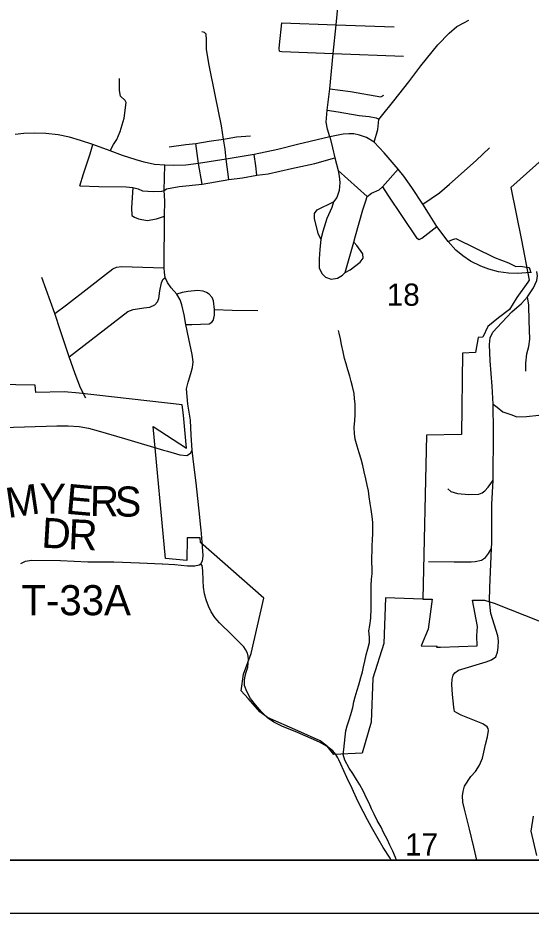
# Model space of a CAD drawing. Extents: x 0 to 34, y 0 to 22.
# Drawn here: x 7.23 to 8.199, y 14 to 15.691 of the extents above; entities that cross this region are included whole.
import ezdxf

# ---------------------------------------------------------------- set-up
doc = ezdxf.new("R2010")
doc.units = 0
for name, color, linetype in [('GM_X_City_Street', 7, 'Continuous'), ('GM_X_Corporation', 7, 'Continuous'), ('GM_X_County_Road', 7, 'Continuous'), ('GM_X_Minor_River', 7, 'Continuous'), ('GM_X_Section_Text', 7, 'Continuous'), ('GM_X_State_Route', 7, 'Continuous'), ('GM_X_Township_Road', 7, 'Continuous'), ('GM_X_Township_Road_Text', 7, 'Continuous'), ('SH_Data', 7, 'Continuous')]:
    doc.layers.add(name, color=color, linetype=linetype)

msp = doc.modelspace()

# ---------------------------------------------------------------- linework, layer by layer
at = {"layer": 'GM_X_City_Street'}
msp.add_line((7.8345, 15.4031), (7.8892, 15.3538), dxfattribs=at)
for points in [[(7.819, 15.4661), (7.8146, 15.4811), (7.8118, 15.4943), (7.8136, 15.5166), (7.8185, 15.5572), (7.8249, 15.6239), (7.8306, 15.6782), (7.8348, 15.7167), (7.8392, 15.7584)], [(7.7236, 15.6285), (7.7232, 15.633), (7.7235, 15.6404), (7.7281, 15.682)], [(7.7281, 15.682), (7.8306, 15.6782), (7.9406, 15.674)], [(7.9026, 15.4564), (7.9093, 15.4801), (7.9116, 15.499), (7.9167, 15.5054), (7.9399, 15.5344), (7.9683, 15.5703), (7.9906, 15.6003), (8.0229, 15.6404), (8.0442, 15.6623), (8.0588, 15.675), (8.0722, 15.682), (8.0815, 15.6868)], [(7.6279, 15.3857), (7.6231, 15.4243), (7.6208, 15.443), (7.6179, 15.4621), (7.6144, 15.4874), (7.6022, 15.5458), (7.5909, 15.602), (7.5859, 15.6311), (7.586, 15.6499), (7.5854, 15.6602), (7.5818, 15.6634), (7.577, 15.6647)], [(7.7236, 15.6285), (7.728, 15.6274), (7.8249, 15.6239), (7.9581, 15.6189)], [(7.404, 15.4399), (7.41, 15.452), (7.4165, 15.4614), (7.4225, 15.4767), (7.4302, 15.5015), (7.434, 15.531), (7.4321, 15.5353), (7.4233, 15.5434), (7.4213, 15.5538), (7.4215, 15.5766)], [(7.8185, 15.5572), (7.8576, 15.552), (7.9151, 15.5419), (7.9205, 15.5454)], [(7.8136, 15.5166), (7.8346, 15.5134), (7.8744, 15.5068), (7.8934, 15.5049), (7.9065, 15.5022), (7.9098, 15.5007), (7.9116, 15.499)], [(7.5156, 15.4475), (7.5467, 15.4517), (7.5655, 15.4538), (7.5907, 15.4583), (7.6179, 15.4621), (7.6427, 15.4664), (7.6688, 15.4681)], [(7.819, 15.4661), (7.8236, 15.4458), (7.8281, 15.4268), (7.8345, 15.4031), (7.8365, 15.3919), (7.8379, 15.3799), (7.8366, 15.3652), (7.8322, 15.3519), (7.826, 15.3437), (7.8223, 15.3331), (7.8132, 15.3119), (7.8056, 15.2874), (7.8015, 15.2734), (7.7997, 15.2537), (7.7984, 15.236), (7.7988, 15.219), (7.8034, 15.2084), (7.8106, 15.2012), (7.8216, 15.1978), (7.8332, 15.1993), (7.8428, 15.2048), (7.8475, 15.2099), (7.8642, 15.2676), (7.8673, 15.2793), (7.8813, 15.3287), (7.8865, 15.3458), (7.8892, 15.3538), (7.8977, 15.3599), (7.9122, 15.3665), (7.9182, 15.3717), (7.9478, 15.4051)], [(7.3463, 15.374), (7.3533, 15.3964), (7.3661, 15.4346), (7.371, 15.4519)], [(7.5774, 15.3768), (7.5707, 15.416), (7.5655, 15.4538)], [(7.9942, 15.3392), (8.0258, 15.3604), (8.0446, 15.3769), (8.0952, 15.4217), (8.1201, 15.4458)], [(7.5061, 15.3653), (7.5103, 15.3684), (7.5344, 15.3725), (7.5774, 15.3768), (7.6279, 15.3857), (7.6537, 15.3888), (7.6811, 15.3942), (7.7024, 15.3968), (7.7466, 15.4065), (7.7903, 15.416), (7.8281, 15.4268)], [(7.6811, 15.3942), (7.6793, 15.4119), (7.6761, 15.4333)], [(7.3463, 15.374), (7.3825, 15.3725), (7.434, 15.3718), (7.4464, 15.3705), (7.457, 15.3684), (7.4651, 15.3647), (7.485, 15.3634), (7.5017, 15.3638), (7.5061, 15.3653)], [(7.4464, 15.3705), (7.4441, 15.3324), (7.445, 15.318), (7.4497, 15.3146), (7.4577, 15.3114), (7.4736, 15.3085), (7.4914, 15.3118), (7.5068, 15.3168)], [(7.9182, 15.3717), (7.9283, 15.356), (7.9828, 15.2753), (7.9873, 15.2726), (7.9923, 15.2747), (8.021, 15.2971)], [(7.8015, 15.2734), (7.797, 15.2839), (7.7896, 15.312), (7.7901, 15.3216), (7.7951, 15.3284), (7.826, 15.3437)], [(8.0423, 15.2685), (8.0494, 15.272), (8.0567, 15.2746), (8.1296, 15.2384), (8.1565, 15.2282), (8.17, 15.2215), (8.1793, 15.2219), (8.1897, 15.2204), (8.1946, 15.2194), (8.1968, 15.2166), (8.198, 15.21)], [(7.8475, 15.2099), (7.8569, 15.2152), (7.8763, 15.2294), (7.882, 15.2375), (7.8814, 15.2452), (7.8701, 15.2612), (7.8642, 15.2676)], [(7.2994, 15.1329), (7.3211, 15.1488), (7.3638, 15.1818), (7.3949, 15.2064), (7.4086, 15.2171), (7.4161, 15.2203), (7.425, 15.2212), (7.5058, 15.2191)], [(8.1204, 14.5894), (8.1209, 14.6149), (8.124, 14.6886), (8.1249, 14.6997), (8.1249, 14.7277), (8.1247, 14.7721), (8.1276, 14.8181), (8.1279, 14.9095), (8.1272, 14.9616), (8.1252, 14.9952), (8.1218, 15.043), (8.1204, 15.0739), (8.1215, 15.0866), (8.1267, 15.0972), (8.1439, 15.1155), (8.1627, 15.1358), (8.1807, 15.1518), (8.1921, 15.1642), (8.2034, 15.1813), (8.21, 15.1948), (8.2108, 15.2036), (8.2097, 15.2121)], [(7.358, 14.9728), (7.3476, 14.9925), (7.3377, 15.0186), (7.3266, 15.051), (7.3102, 15.0999), (7.2994, 15.1329), (7.2748, 15.2007)], [(7.3266, 15.051), (7.437, 15.1363), (7.4472, 15.1404), (7.4674, 15.1434), (7.4788, 15.1448), (7.4884, 15.1489), (7.4934, 15.1544), (7.4959, 15.1613), (7.4975, 15.1752), (7.5007, 15.1907), (7.5032, 15.1971), (7.5077, 15.2007)], [(7.5471, 15.1117), (7.5584, 15.1121), (7.5911, 15.1133), (7.5961, 15.1163), (7.5985, 15.1194), (7.6, 15.1241), (7.6007, 15.1296), (7.6011, 15.1402), (7.5989, 15.1564), (7.5965, 15.1631), (7.5909, 15.1693), (7.5859, 15.1724), (7.5796, 15.175), (7.5686, 15.1761), (7.5513, 15.1744), (7.5397, 15.1725), (7.5297, 15.1691)], [(8.1891, 15.0239), (8.1893, 15.0386), (8.1911, 15.0566), (8.195, 15.0701), (8.1968, 15.0841), (8.1954, 15.1185), (8.1944, 15.1485), (8.1921, 15.1642)], [(7.6011, 15.1402), (7.6346, 15.1387), (7.683, 15.1384)], [(8.1272, 14.9616), (8.1347, 14.9558), (8.1454, 14.9471), (8.1608, 14.9416), (8.1721, 14.9376), (8.1904, 14.938), (8.2139, 14.9407)], [(8.042, 14.8013), (8.0476, 14.7966), (8.0601, 14.7924), (8.0815, 14.7908), (8.1004, 14.7916), (8.1064, 14.7941), (8.1116, 14.7975), (8.1179, 14.8043), (8.1229, 14.8113), (8.1276, 14.8181)], [(8.0054, 14.6639), (8.0536, 14.6635), (8.0767, 14.6634), (8.086, 14.6636), (8.0935, 14.6642), (8.1055, 14.6669), (8.113, 14.6717), (8.1183, 14.6791), (8.124, 14.6886)]]:
    msp.add_lwpolyline(points, dxfattribs=at)
at = {"layer": 'GM_X_Corporation'}
for points in [[(4.5503, 14.1), (8.9, 14.1), (8.9, 15.6953), (8.4164, 15.7046), (8.4088, 15.7047), (8.2556, 15.7096), (8.2436, 15.7079), (8.2379, 15.708), (7.8346, 15.7173), (7.3532, 15.7283), (7.2238, 15.7321), (7.2174, 15.7331), (7.1916, 15.7337), (7.0294, 15.7382), (6.9267, 15.7411), (6.8653, 15.7428), (6.8105, 15.7443), (6.4702, 15.7474), (5.7944, 15.7634), (5.6123, 15.7657), (5.6068, 15.7657), (5.6014, 15.7658), (5.4664, 15.7674)], [(8.2554, 15.4553), (8.1604, 15.3705), (8.1807, 15.2712), (8.1955, 15.1955), (8.1929, 15.1917), (8.1718, 15.1627), (8.1582, 15.14), (8.1376, 15.1245), (8.1175, 15.108), (8.1077, 15.0882), (8.0992, 15.0873), (8.0942, 15.059), (8.0692, 15.058), (8.0677, 14.9042), (8.0011, 14.9029), (7.9943, 14.5933), (7.9241, 14.5958), (7.9211, 14.5094), (7.8998, 14.4439), (7.8968, 14.3609), (7.88, 14.3022), (7.8265, 14.2995), (7.8137, 14.3155), (7.8003, 14.3256), (7.7585, 14.3443), (7.7009, 14.3696), (7.6864, 14.38), (7.6648, 14.4053), (7.6516, 14.4201), (7.6558, 14.4513), (7.6701, 14.4906), (7.6944, 14.5951), (7.5746, 14.7003), (7.5738, 14.7092), (7.5496, 14.7086), (7.5487, 14.6662), (7.5081, 14.67), (7.4849, 14.9192), (7.5483, 14.878), (7.5426, 14.9403), (7.5396, 14.96), (7.3453, 14.982), (7.3172, 14.9845), (7.2635, 14.9834), (7.2621, 14.9971), (7.0789, 15.0004)], [(8.2554, 15.4553), (8.1604, 15.3705), (8.1807, 15.2712), (8.1955, 15.1955), (8.1929, 15.1917), (8.1718, 15.1627), (8.1582, 15.14), (8.1376, 15.1245), (8.1175, 15.108), (8.1077, 15.0882), (8.0992, 15.0873), (8.0942, 15.059), (8.0692, 15.058), (8.0677, 14.9042), (8.0011, 14.9029), (7.9943, 14.5933), (8.0119, 14.5929), (8.0044, 14.5363), (7.9916, 14.5046), (8.0213, 14.504), (8.0206, 14.5025), (8.0249, 14.5024), (8.028, 14.5025), (8.0971, 14.5048), (8.0965, 14.5235), (8.0978, 14.5412), (8.0881, 14.5914), (8.1109, 14.591), (8.1291, 14.5852), (8.2738, 14.5284)], [(8.2032, 14.1833), (8.1986, 14.1545), (8.2091, 14.1089)]]:
    msp.add_lwpolyline(points, dxfattribs=at)
at = {"layer": 'GM_X_County_Road'}
msp.add_line((7.5586, 14.8746), (7.5571, 14.9028), dxfattribs=at)
for points in [[(7.5516, 15.0046), (7.5564, 15.0194), (7.5593, 15.0305), (7.5604, 15.0415), (7.5593, 15.0511), (7.5588, 15.0551), (7.5525, 15.0849), (7.5471, 15.1117), (7.5434, 15.1299), (7.5392, 15.1492), (7.5363, 15.1583), (7.5297, 15.1691), (7.5191, 15.181), (7.512, 15.1915), (7.5077, 15.2007), (7.5063, 15.21), (7.5058, 15.2191), (7.5068, 15.3168), (7.507, 15.3455), (7.5061, 15.3653), (7.5069, 15.4128)], [(7.5571, 14.9028), (7.5555, 14.931), (7.5508, 14.9615), (7.5495, 14.9758), (7.5481, 14.9903), (7.551, 15.0028), (7.5516, 15.0046)], [(7.2014, 14.9171), (7.3033, 14.9206), (7.3248, 14.9206), (7.3453, 14.9191), (7.3632, 14.9158), (7.3815, 14.9111), (7.4311, 14.8965), (7.5045, 14.8746)], [(7.5045, 14.8746), (7.5123, 14.8723), (7.5357, 14.8659), (7.5486, 14.8646), (7.5559, 14.8689), (7.5586, 14.8746)]]:
    msp.add_lwpolyline(points, dxfattribs=at)
at = {"layer": 'GM_X_Minor_River'}
for points in [[(7.9275, 14.1381), (7.9204, 14.1525), (7.9156, 14.1622), (7.9085, 14.175), (7.9026, 14.1867), (7.8978, 14.1969), (7.8931, 14.2074), (7.8883, 14.2172), (7.8823, 14.23), (7.8753, 14.2425), (7.8694, 14.2522), (7.8623, 14.2635), (7.8556, 14.274), (7.8473, 14.2887), (7.8441, 14.2993), (7.845, 14.3092), (7.8467, 14.321), (7.8476, 14.3328), (7.8492, 14.3442), (7.8517, 14.3538), (7.8556, 14.3653), (7.8585, 14.3752), (7.862, 14.3886), (7.8641, 14.3989), (7.8669, 14.4084), (7.8705, 14.4211), (7.8733, 14.431), (7.8776, 14.4448), (7.8804, 14.4555), (7.8825, 14.465), (7.8849, 14.4761), (7.8877, 14.4879), (7.8905, 14.499), (7.8937, 14.5112), (7.8939, 14.5215), (7.8925, 14.5329), (7.8942, 14.5432), (7.8962, 14.5573), (7.8966, 14.5755), (7.8967, 14.5854), (7.8969, 14.5976), (7.8967, 14.6082), (7.8968, 14.6189), (7.8977, 14.6311), (7.8987, 14.6406), (7.898, 14.6729), (7.8986, 14.6828), (7.8987, 14.6934), (7.8996, 14.7056), (7.8998, 14.7163), (7.8999, 14.7281), (7.9001, 14.7376), (7.8987, 14.7493), (7.8969, 14.7622), (7.8952, 14.7736), (7.8934, 14.7861), (7.8917, 14.7975), (7.8895, 14.8081), (7.8866, 14.8202), (7.8837, 14.8334), (7.8812, 14.8456), (7.8779, 14.8577), (7.8739, 14.8694), (7.8702, 14.8818), (7.8669, 14.8955), (7.8655, 14.9057), (7.8649, 14.9171), (7.8661, 14.9308), (7.8667, 14.9415), (7.8665, 14.951), (7.8667, 14.9616), (7.8657, 14.9722), (7.8647, 14.9817), (7.8618, 14.9946), (7.8593, 15.0044), (7.8565, 15.0146), (7.8528, 15.026), (7.8495, 15.0377), (7.8463, 15.0479), (7.8437, 15.0604), (7.8408, 15.074), (7.8387, 15.085), (7.8366, 15.0956), (7.8353, 15.1005)], [(7.945, 14.1), (7.9426, 14.105), (7.9378, 14.1171), (7.9319, 14.1283), (7.9275, 14.1381)]]:
    msp.add_lwpolyline(points, dxfattribs=at)
at = {"layer": 'GM_X_State_Route'}
msp.add_lwpolyline([(8.1999, 15.2103), (8.198, 15.21), (8.1733, 15.2081), (8.156, 15.2086), (8.1374, 15.2112), (8.119, 15.2164), (8.1042, 15.2219), (8.0845, 15.2318), (8.07, 15.2414), (8.0565, 15.2521), (8.0423, 15.2685), (8.021, 15.2971), (8.0049, 15.3223), (7.9942, 15.3392), (7.9737, 15.3706), (7.9586, 15.3919), (7.9478, 15.4051), (7.9213, 15.4364), (7.9026, 15.4564), (7.8883, 15.4649), (7.8747, 15.4698), (7.8642, 15.4718), (7.8548, 15.4722), (7.8442, 15.4714), (7.819, 15.4661), (7.7577, 15.452), (7.7208, 15.4424), (7.6761, 15.4333), (7.6231, 15.4243), (7.5707, 15.416), (7.547, 15.4129), (7.5232, 15.412), (7.5069, 15.4128), (7.4879, 15.4141), (7.4679, 15.4183), (7.4527, 15.4228), (7.4272, 15.4314), (7.404, 15.4399), (7.371, 15.4519), (7.3476, 15.4596), (7.3269, 15.4656), (7.3056, 15.4701), (7.2822, 15.4727), (7.261, 15.4734), (7.2407, 15.4724), (7.2243, 15.4708)], dxfattribs=at)
at = {"layer": 'GM_X_Township_Road'}
msp.add_line((7.5752, 14.7282), (7.5732, 14.7477), dxfattribs=at)
for points in [[(7.5732, 14.7477), (7.5664, 14.813), (7.5612, 14.8522), (7.5586, 14.8746)], [(7.5769, 14.7086), (7.5756, 14.7243), (7.5752, 14.7282)], [(7.5789, 14.6692), (7.5796, 14.6757), (7.5776, 14.6998), (7.5769, 14.7086)], [(7.2349, 14.6606), (7.244, 14.665), (7.2552, 14.6668), (7.3101, 14.6658), (7.3619, 14.6638), (7.4108, 14.6633), (7.4594, 14.6618), (7.5018, 14.6599), (7.503, 14.6598)], [(7.6609, 14.455), (7.6639, 14.4646), (7.6649, 14.4795), (7.6645, 14.4855), (7.6632, 14.4911), (7.6596, 14.4982), (7.6562, 14.5028), (7.6521, 14.5071), (7.6342, 14.5248), (7.6104, 14.5482), (7.6017, 14.5585), (7.5947, 14.5694), (7.5897, 14.5801), (7.5852, 14.5918), (7.5822, 14.6034), (7.5803, 14.6156), (7.5796, 14.6284), (7.579, 14.647), (7.5777, 14.6568), (7.5751, 14.6596), (7.5785, 14.6656), (7.5789, 14.6692)], [(7.503, 14.6598), (7.5258, 14.6584), (7.5502, 14.6562), (7.5514, 14.6562)], [(7.5514, 14.6562), (7.564, 14.6561), (7.5718, 14.6577), (7.5751, 14.6596)], [(8.0964, 14.1), (8.0906, 14.1245), (8.0828, 14.1588), (8.073, 14.1962), (8.0699, 14.2096), (8.0692, 14.2217), (8.0706, 14.2299), (8.0734, 14.2397), (8.0853, 14.2578), (8.0937, 14.2675), (8.1016, 14.2792), (8.1071, 14.2927), (8.1098, 14.3042), (8.113, 14.3186), (8.1165, 14.3331), (8.1186, 14.3451), (8.1182, 14.3489), (8.1161, 14.3521), (8.1076, 14.3578), (8.0666, 14.3742), (8.059, 14.3784), (8.0546, 14.381), (8.0534, 14.3849), (8.0532, 14.3889), (8.0506, 14.4132), (8.0493, 14.4316), (8.0499, 14.4417), (8.0519, 14.4493), (8.0548, 14.4541), (8.0621, 14.4589), (8.1141, 14.4746), (8.1239, 14.4787), (8.1322, 14.4844), (8.1356, 14.4929), (8.1368, 14.502), (8.1373, 14.5145), (8.1362, 14.5235), (8.1231, 14.5658), (8.1204, 14.5894)], [(7.8337, 14.2932), (7.8299, 14.2997), (7.8246, 14.3064), (7.8139, 14.315), (7.7992, 14.3226), (7.7577, 14.3411), (7.7284, 14.353), (7.7128, 14.3606), (7.701, 14.369), (7.6899, 14.3802), (7.6785, 14.3933), (7.6692, 14.4053), (7.6619, 14.4186), (7.6579, 14.4301), (7.6575, 14.44), (7.6588, 14.4483), (7.6609, 14.455)], [(7.9347, 14.1), (7.9329, 14.1035), (7.9198, 14.1242), (7.9098, 14.1402), (7.8972, 14.1625), (7.89, 14.1759), (7.8816, 14.1921), (7.872, 14.2117), (7.8608, 14.2354), (7.8509, 14.2564), (7.8396, 14.2813), (7.8358, 14.2896), (7.8337, 14.2932)]]:
    msp.add_lwpolyline(points, dxfattribs=at)
at = {"layer": 'SH_Data'}
msp.add_line((2, 14), (9, 14), dxfattribs=at)
msp.add_lwpolyline([(2.1, 20.9), (8.9, 20.9), (8.9, 14.1), (2.1, 14.1)], close=True, dxfattribs=at)

# ---------------------------------------------------------------- texts
at = {"layer": 'GM_X_Section_Text'}
for s, p in [('18', (7.9264, 15.1473)), ('17', (7.961, 14.1087))]:
    msp.add_text(s, height=0.04186, rotation=0, dxfattribs=at).set_placement(p)
at = {"layer": 'GM_X_Township_Road_Text'}
for s, height, rotation, p in [('M', 0.0568, 8.4304, (7.211, 14.7461)), ('Y', 0.0568, 359.4609, (7.2696, 14.755)), ('E', 0.0568, 354.8719, (7.3184, 14.7546)), ('R', 0.0568, 358.7859, (7.365, 14.7505)), ('S', 0.0568, 358.949, (7.4118, 14.7495)), ('D', 0.0568, 356.6395, (7.2731, 14.6906)), ('R', 0.0568, 357.4514, (7.3239, 14.6876)), ('T-33A', 0.05682, 0.002, (7.2361, 14.5627))]:
    msp.add_text(s, height=height, rotation=rotation, dxfattribs=at).set_placement(p)

doc.saveas('drawing.dxf')
